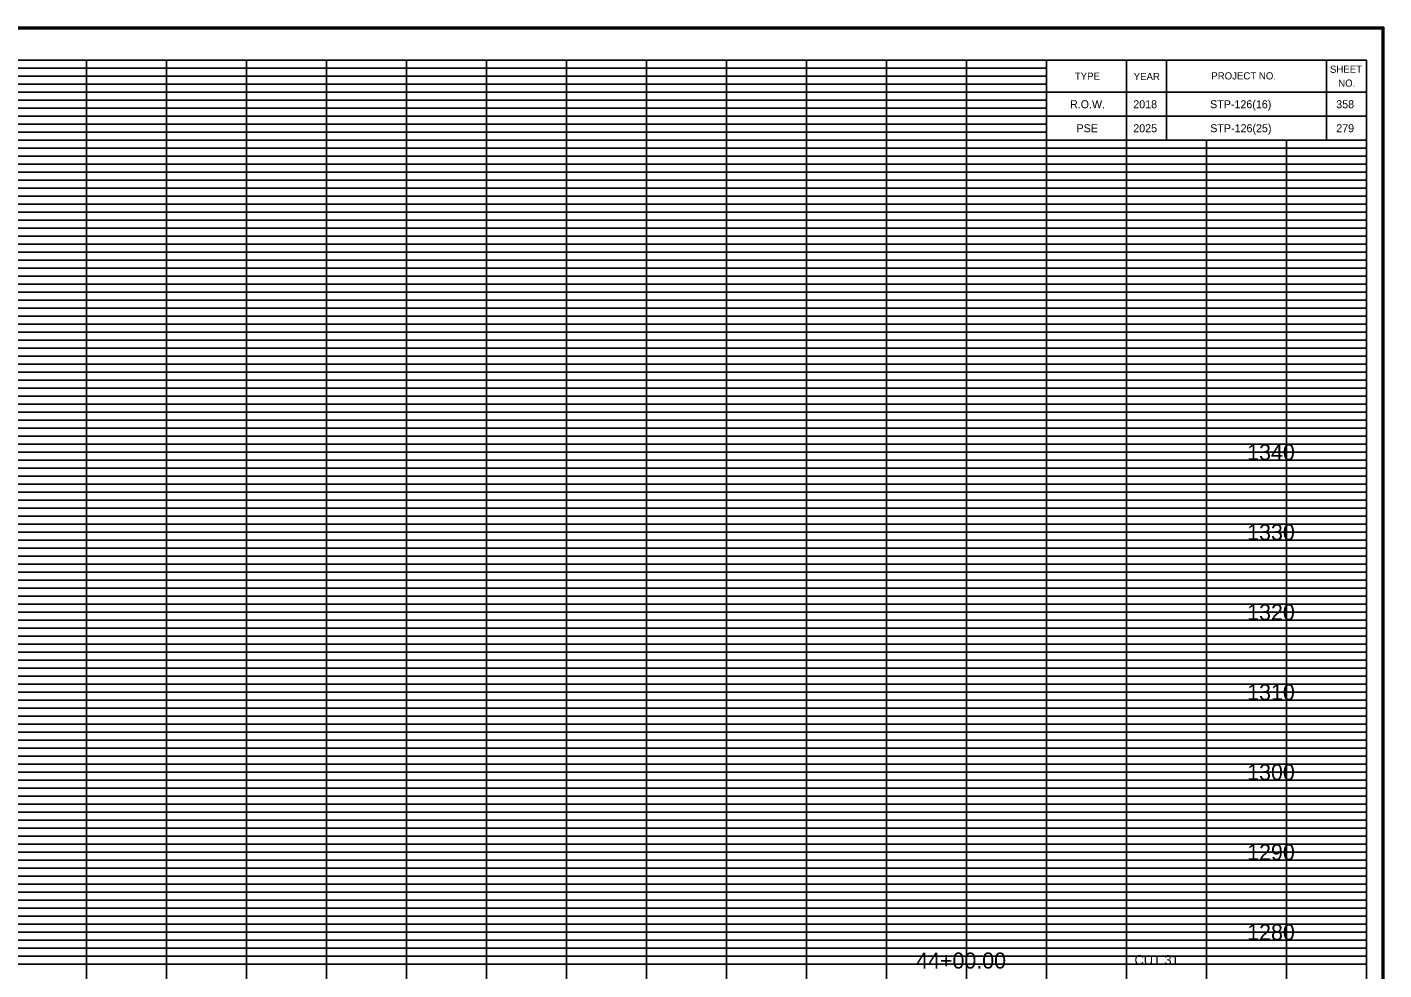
# Model space of a CAD drawing. Extents: x 980 to 1324, y 978 to 2847.
# Drawn here: x 1152.6 to 1322.2, y 1366.3 to 1484.1 of the extents above; entities that cross this region are included whole.
import ezdxf

# ---------------------------------------------------------------- set-up
doc = ezdxf.new("R2010")
doc.units = 0
for name, color, linetype in [('DESIGN - SCRATCH - User 1', 7, 'Continuous'), ('DESIGN - SHEET - Corner Text', 7, 'Continuous'), ('DESIGN - SHEET - Light Grid', 7, 'Continuous'), ('DESIGN - SHEET - Linework', 7, 'Continuous'), ('DESIGN - SHEET - Plot Shape', 7, 'Continuous'), ('DESIGN - TYPICAL - Text', 7, 'Continuous')]:
    doc.layers.add(name, color=color, linetype=linetype)

# ---------------------------------------------------------------- blocks, each defined once
blk = doc.blocks.new('XSTSHT')
at = {"layer": 'DESIGN - SCRATCH - User 1'}
for p, q in [((28.5, 20.45), (28.5, 20.45)), ((29.24, 20.45), (29.24, 20.45)), ((30.49, 20.45), (30.49, 20.45)), ((31.74, 20.45), (31.74, 20.45)), ((28.5, 20.15), (28.5, 20.15)), ((29.24, 20.15), (29.24, 20.15)), ((30.49, 20.15), (30.49, 20.15)), ((31.74, 20.15), (31.74, 20.15))]:
    blk.add_line(p, q, dxfattribs=at)
at = {"layer": 'DESIGN - SHEET - Light Grid'}
for p, q in [((8, 20.9), (16, 20.9)), ((16, 20.9), (24, 20.9)), ((24, 20.9), (28, 20.9)), ((8, 20.8), (16, 20.8)), ((8, 20.7), (16, 20.7)), ((16, 20.8), (24, 20.8)), ((16, 20.7), (24, 20.7)), ((24, 20.8), (28, 20.8)), ((24, 20.7), (28, 20.7)), ((8, 20.6), (16, 20.6)), ((16, 20.6), (24, 20.6)), ((24, 20.6), (28, 20.6)), ((8, 20.5), (16, 20.5)), ((8, 20.4), (16, 20.4)), ((16, 20.5), (24, 20.5)), ((16, 20.4), (24, 20.4)), ((24, 20.5), (28, 20.5)), ((24, 20.4), (28, 20.4)), ((8, 20.3), (16, 20.3)), ((8, 20.2), (16, 20.2)), ((16, 20.3), (24, 20.3)), ((16, 20.2), (24, 20.2)), ((24, 20.3), (28, 20.3)), ((24, 20.2), (28, 20.2)), ((8, 20.1), (16, 20.1)), ((16, 20.1), (24, 20.1)), ((24, 20.1), (28, 20.1)), ((8, 19.9), (16, 19.9)), ((16, 19.9), (24, 19.9)), ((24, 19.9), (32, 19.9)), ((8, 19.8), (16, 19.8)), ((8, 19.7), (16, 19.7)), ((16, 19.8), (24, 19.8)), ((16, 19.7), (24, 19.7)), ((24, 19.8), (32, 19.8)), ((24, 19.7), (32, 19.7)), ((8, 19.6), (16, 19.6)), ((16, 19.6), (24, 19.6)), ((24, 19.6), (32, 19.6)), ((8, 19.5), (16, 19.5)), ((8, 19.4), (16, 19.4)), ((16, 19.5), (24, 19.5)), ((16, 19.4), (24, 19.4)), ((24, 19.5), (32, 19.5)), ((24, 19.4), (32, 19.4)), ((8, 19.3), (16, 19.3)), ((8, 19.2), (16, 19.2)), ((16, 19.3), (24, 19.3)), ((16, 19.2), (24, 19.2)), ((24, 19.3), (32, 19.3)), ((24, 19.2), (32, 19.2)), ((8, 19.1), (16, 19.1)), ((16, 19.1), (24, 19.1)), ((24, 19.1), (32, 19.1)), ((8, 18.9), (16, 18.9)), ((16, 18.9), (24, 18.9)), ((24, 18.9), (32, 18.9)), ((8, 18.8), (16, 18.8)), ((8, 18.7), (16, 18.7)), ((16, 18.8), (24, 18.8)), ((16, 18.7), (24, 18.7)), ((24, 18.8), (32, 18.8)), ((24, 18.7), (32, 18.7)), ((8, 18.6), (16, 18.6)), ((8, 18.5), (16, 18.5)), ((16, 18.6), (24, 18.6)), ((16, 18.5), (24, 18.5)), ((24, 18.6), (32, 18.6)), ((24, 18.5), (32, 18.5)), ((8, 18.4), (16, 18.4)), ((16, 18.4), (24, 18.4)), ((24, 18.4), (32, 18.4)), ((8, 18.3), (16, 18.3)), ((8, 18.2), (16, 18.2)), ((16, 18.3), (24, 18.3)), ((16, 18.2), (24, 18.2)), ((24, 18.3), (32, 18.3)), ((24, 18.2), (32, 18.2)), ((8, 18.1), (16, 18.1)), ((16, 18.1), (24, 18.1)), ((24, 18.1), (32, 18.1)), ((8, 17.9), (16, 17.9)), ((16, 17.9), (24, 17.9)), ((24, 17.9), (32, 17.9)), ((8, 17.8), (16, 17.8)), ((8, 17.7), (16, 17.7)), ((16, 17.8), (24, 17.8)), ((16, 17.7), (24, 17.7)), ((24, 17.8), (32, 17.8)), ((24, 17.7), (32, 17.7)), ((8, 17.6), (16, 17.6)), ((8, 17.5), (16, 17.5)), ((16, 17.6), (24, 17.6)), ((16, 17.5), (24, 17.5)), ((24, 17.6), (32, 17.6)), ((24, 17.5), (32, 17.5)), ((8, 17.4), (16, 17.4)), ((8, 17.3), (16, 17.3)), ((16, 17.4), (24, 17.4)), ((16, 17.3), (24, 17.3)), ((24, 17.4), (32, 17.4)), ((24, 17.3), (32, 17.3)), ((8, 17.2), (16, 17.2)), ((16, 17.2), (24, 17.2)), ((24, 17.2), (32, 17.2)), ((8, 17.1), (16, 17.1)), ((16, 17.1), (24, 17.1)), ((24, 17.1), (32, 17.1)), ((8, 16.9), (16, 16.9)), ((8, 16.8), (16, 16.8)), ((16, 16.9), (24, 16.9)), ((16, 16.8), (24, 16.8)), ((24, 16.9), (32, 16.9)), ((24, 16.8), (32, 16.8)), ((8, 16.7), (16, 16.7)), ((16, 16.7), (24, 16.7)), ((24, 16.7), (32, 16.7)), ((8, 16.6), (16, 16.6)), ((8, 16.5), (16, 16.5)), ((16, 16.6), (24, 16.6)), ((16, 16.5), (24, 16.5)), ((24, 16.6), (32, 16.6)), ((24, 16.5), (32, 16.5)), ((8, 16.4), (16, 16.4)), ((8, 16.3), (16, 16.3)), ((16, 16.4), (24, 16.4)), ((16, 16.3), (24, 16.3)), ((24, 16.4), (32, 16.4)), ((24, 16.3), (32, 16.3)), ((8, 16.2), (16, 16.2)), ((16, 16.2), (24, 16.2)), ((24, 16.2), (32, 16.2)), ((8, 16.1), (16, 16.1)), ((16, 16.1), (24, 16.1)), ((24, 16.1), (32, 16.1)), ((8, 15.9), (16, 15.9)), ((8, 15.8), (16, 15.8)), ((16, 15.9), (24, 15.9)), ((16, 15.8), (24, 15.8)), ((24, 15.9), (32, 15.9)), ((24, 15.8), (32, 15.8)), ((8, 15.7), (16, 15.7)), ((16, 15.7), (24, 15.7)), ((24, 15.7), (32, 15.7)), ((8, 15.6), (16, 15.6)), ((8, 15.5), (16, 15.5)), ((16, 15.6), (24, 15.6)), ((16, 15.5), (24, 15.5)), ((24, 15.6), (32, 15.6)), ((24, 15.5), (32, 15.5)), ((8, 15.4), (16, 15.4)), ((8, 15.3), (16, 15.3)), ((16, 15.4), (24, 15.4)), ((16, 15.3), (24, 15.3)), ((24, 15.4), (32, 15.4)), ((24, 15.3), (32, 15.3)), ((8, 15.2), (16, 15.2)), ((8, 15.1), (16, 15.1)), ((16, 15.2), (24, 15.2)), ((16, 15.1), (24, 15.1)), ((24, 15.2), (32, 15.2)), ((24, 15.1), (32, 15.1)), ((8, 14.9), (16, 14.9)), ((8, 14.8), (16, 14.8)), ((16, 14.9), (24, 14.9)), ((16, 14.8), (24, 14.8)), ((24, 14.9), (32, 14.9)), ((24, 14.8), (32, 14.8)), ((8, 14.7), (16, 14.7)), ((8, 14.6), (16, 14.6)), ((16, 14.7), (24, 14.7)), ((16, 14.6), (24, 14.6)), ((24, 14.7), (32, 14.7)), ((24, 14.6), (32, 14.6)), ((8, 14.5), (16, 14.5)), ((16, 14.5), (24, 14.5)), ((24, 14.5), (32, 14.5)), ((8, 14.4), (16, 14.4)), ((8, 14.3), (16, 14.3)), ((16, 14.4), (24, 14.4)), ((16, 14.3), (24, 14.3)), ((24, 14.4), (32, 14.4)), ((24, 14.3), (32, 14.3)), ((8, 14.2), (16, 14.2)), ((8, 14.1), (16, 14.1)), ((16, 14.2), (24, 14.2)), ((16, 14.1), (24, 14.1)), ((24, 14.2), (32, 14.2)), ((24, 14.1), (32, 14.1)), ((8, 13.9), (16, 13.9)), ((8, 13.8), (16, 13.8)), ((16, 13.9), (24, 13.9)), ((16, 13.8), (24, 13.8)), ((24, 13.9), (32, 13.9)), ((24, 13.8), (32, 13.8)), ((8, 13.7), (16, 13.7)), ((8, 13.6), (16, 13.6)), ((16, 13.7), (24, 13.7)), ((16, 13.6), (24, 13.6)), ((24, 13.7), (32, 13.7)), ((24, 13.6), (32, 13.6)), ((8, 13.5), (16, 13.5)), ((8, 13.4), (16, 13.4)), ((16, 13.5), (24, 13.5)), ((16, 13.4), (24, 13.4)), ((24, 13.5), (32, 13.5)), ((24, 13.4), (32, 13.4)), ((8, 13.3), (16, 13.3)), ((16, 13.3), (24, 13.3)), ((24, 13.3), (32, 13.3)), ((8, 13.2), (16, 13.2)), ((8, 13.1), (16, 13.1)), ((16, 13.2), (24, 13.2)), ((16, 13.1), (24, 13.1)), ((24, 13.2), (32, 13.2)), ((24, 13.1), (32, 13.1)), ((8, 12.9), (16, 12.9)), ((16, 12.9), (24, 12.9)), ((24, 12.9), (32, 12.9)), ((8, 12.8), (16, 12.8)), ((16, 12.8), (24, 12.8)), ((24, 12.8), (32, 12.8)), ((8, 12.7), (16, 12.7)), ((8, 12.6), (16, 12.6)), ((16, 12.7), (24, 12.7)), ((16, 12.6), (24, 12.6)), ((24, 12.7), (32, 12.7)), ((24, 12.6), (32, 12.6)), ((8, 12.5), (16, 12.5)), ((8, 12.4), (16, 12.4)), ((16, 12.5), (24, 12.5)), ((16, 12.4), (24, 12.4)), ((24, 12.5), (32, 12.5)), ((24, 12.4), (32, 12.4)), ((8, 12.3), (16, 12.3)), ((16, 12.3), (24, 12.3)), ((24, 12.3), (32, 12.3)), ((8, 12.2), (16, 12.2)), ((8, 12.1), (16, 12.1)), ((16, 12.2), (24, 12.2)), ((16, 12.1), (24, 12.1)), ((24, 12.2), (32, 12.2)), ((24, 12.1), (32, 12.1)), ((8, 11.9), (16, 11.9)), ((16, 11.9), (24, 11.9)), ((24, 11.9), (32, 11.9)), ((8, 11.8), (16, 11.8)), ((16, 11.8), (24, 11.8)), ((24, 11.8), (32, 11.8)), ((8, 11.7), (16, 11.7)), ((8, 11.6), (16, 11.6)), ((16, 11.7), (24, 11.7)), ((16, 11.6), (24, 11.6)), ((24, 11.7), (32, 11.7)), ((24, 11.6), (32, 11.6)), ((8, 11.5), (16, 11.5)), ((8, 11.4), (16, 11.4)), ((16, 11.5), (24, 11.5)), ((16, 11.4), (24, 11.4)), ((24, 11.5), (32, 11.5)), ((24, 11.4), (32, 11.4)), ((8, 11.3), (16, 11.3)), ((8, 11.2), (16, 11.2)), ((16, 11.3), (24, 11.3)), ((16, 11.2), (24, 11.2)), ((24, 11.3), (32, 11.3)), ((24, 11.2), (32, 11.2)), ((8, 11.1), (16, 11.1)), ((16, 11.1), (24, 11.1)), ((24, 11.1), (32, 11.1)), ((8, 10.9), (16, 10.9)), ((16, 10.9), (24, 10.9)), ((24, 10.9), (32, 10.9)), ((8, 10.8), (16, 10.8)), ((8, 10.7), (16, 10.7)), ((16, 10.8), (24, 10.8)), ((16, 10.7), (24, 10.7)), ((24, 10.8), (32, 10.8)), ((24, 10.7), (32, 10.7)), ((8, 10.6), (16, 10.6)), ((16, 10.6), (24, 10.6)), ((24, 10.6), (32, 10.6)), ((8, 10.5), (16, 10.5)), ((8, 10.4), (16, 10.4)), ((16, 10.5), (24, 10.5)), ((16, 10.4), (24, 10.4)), ((24, 10.5), (32, 10.5)), ((24, 10.4), (32, 10.4)), ((8, 10.3), (16, 10.3)), ((8, 10.2), (16, 10.2)), ((16, 10.3), (24, 10.3)), ((16, 10.2), (24, 10.2)), ((24, 10.3), (32, 10.3)), ((24, 10.2), (32, 10.2)), ((8, 10.1), (16, 10.1)), ((16, 10.1), (24, 10.1)), ((24, 10.1), (32, 10.1)), ((8, 9.9), (16, 9.9)), ((16, 9.9), (24, 9.9)), ((24, 9.9), (32, 9.9)), ((8, 9.8), (16, 9.8)), ((8, 9.7), (16, 9.7)), ((16, 9.8), (24, 9.8)), ((16, 9.7), (24, 9.7)), ((24, 9.8), (32, 9.8)), ((24, 9.7), (32, 9.7))]:
    blk.add_line(p, q, dxfattribs=at)
at = {"layer": 'DESIGN - SHEET - Linework'}
for p, q in [((-1.823, 21.414), (32.217, 21.414)), ((32.217, 21.414), (32.217, -0.414)), ((16, 0), (16, 21)), ((17, 0), (17, 21)), ((18, 0), (18, 21)), ((19, 0), (19, 21)), ((20, 0), (20, 21)), ((21, 0), (21, 21)), ((22, 0), (22, 21)), ((23, 0), (23, 21)), ((24, 0), (24, 21)), ((25, 0), (25, 21)), ((26, 0), (26, 21)), ((27, 0), (27, 21)), ((0, 20), (28, 20)), ((28, 0), (28, 20)), ((29, 0), (29, 20)), ((30, 0), (30, 20)), ((31, 0), (31, 20)), ((0, 19), (32, 19)), ((0, 18), (32, 18)), ((0, 17), (32, 17)), ((0, 16), (32, 16)), ((0, 15), (32, 15)), ((0, 14), (32, 14)), ((0, 13), (32, 13)), ((0, 12), (32, 12)), ((0, 11), (32, 11)), ((0, 10), (32, 10))]:
    blk.add_line(p, q, dxfattribs=at)
for points in [[(0, 21), (0, 0), (32, 0), (32, 21), (0, 21)], [(28, 21), (28, 20), (32, 20), (32, 21), (31.5, 21), (31.5, 20), (29.5, 20), (29.5, 21), (29, 21), (29, 20), (32, 20), (28, 20), (28, 20.3), (32, 20.3), (32, 20.6), (28, 20.6)]]:
    blk.add_lwpolyline(points, dxfattribs=at)
at = {"layer": 'DESIGN - SHEET - Plot Shape'}
for points in [[(-1.803, 21.394), (32.197, 21.394), (32.197, -0.394), (-1.803, -0.394)], [(-0.85, 21), (32, 21), (32, -0.25), (-0.85, -0.25)]]:
    blk.add_lwpolyline(points, close=True, dxfattribs=at)
at = {"layer": 'DESIGN - SHEET - Corner Text'}
for s, p in [('SHEET', (31.543, 20.843)), ('TYPE', (28.354, 20.756)), ('YEAR', (29.09, 20.752)), ('PROJECT NO.', (30.06, 20.76)), ('NO.', (31.646, 20.669))]:
    blk.add_text(s, height=0.09, dxfattribs=at).set_placement(p)

msp = doc.modelspace()

# ---------------------------------------------------------------- linework, layer by layer
at = {"layer": 'DESIGN - SHEET - Plot Shape'}
msp.add_lwpolyline([(991.5, 1267.5), (1320, 1267.5), (1320, 1480), (991.5, 1480)], close=True, dxfattribs=at)

# ---------------------------------------------------------------- block references
at = {"layer": 'DESIGN - SHEET - Plot Shape', "xscale": 10, "yscale": 10}
msp.add_blockref('XSTSHT', (1000, 1270), dxfattribs=at)

# ---------------------------------------------------------------- texts
at = {"layer": 'DESIGN - SHEET - Corner Text'}
for s, p in [('R.O.W.', (1282.94, 1474)), ('2018', (1290.85, 1474)), ('STP-126(16)', (1300.45, 1474)), ('358', (1316.22, 1474)), ('PSE', (1283.75, 1471)), ('2025', (1290.85, 1471)), ('STP-126(25)', (1300.47, 1471)), ('279', (1316.22, 1471))]:
    msp.add_text(s, height=1, dxfattribs=at).set_placement(p)
at = {"layer": 'DESIGN - TYPICAL - Text'}
for s, height, p in [('     1340     ', 2, (1301.37, 1430)), ('     1330     ', 2, (1301.37, 1420)), ('     1320     ', 2, (1301.37, 1410)), ('     1310     ', 2, (1301.37, 1400)), ('     1300     ', 2, (1301.37, 1390)), ('     1290     ', 2, (1301.37, 1380)), ('     1280     ', 2, (1301.37, 1370)), ('     44+00.00     ', 2, (1260, 1366.45)), ('CUT 31', 1.2, (1291, 1366.92))]:
    msp.add_text(s, height=height, dxfattribs=at).set_placement(p)

doc.saveas('drawing.dxf')
